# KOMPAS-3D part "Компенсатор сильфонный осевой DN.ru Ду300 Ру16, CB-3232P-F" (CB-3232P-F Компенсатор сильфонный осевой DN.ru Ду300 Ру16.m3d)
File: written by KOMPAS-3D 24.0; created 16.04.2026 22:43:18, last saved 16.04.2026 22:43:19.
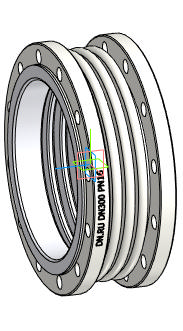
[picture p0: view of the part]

Document properties: Автор: DN.RU; Полное имя файла: D:\PROJECT CAD\DN.RU\..199(ACTUALE). CB-3232P-F Компенсатор сильфонный осевой DN.ru\Исходники\DN300\CB-3232P-F Компенсатор сильфонный осевой DN.ru Ду300 Ру16.m3d

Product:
- Body: Твердое тело1  | qty 1
    Масса: 50.686411
- Part/product: Компенсатор сильфонный осевой DN.ru Ду300 Ру16  | designation CB-3232P-F
    Масса: 40.9
    Раздел спецификации: Прочие изделия
    Комментарий: D140-02146
    Примечание: D140-02146
    additional columns: Типовые

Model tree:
1. Твердое тело1  (labels: Твердое тело1)

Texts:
  CB-3232P-F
